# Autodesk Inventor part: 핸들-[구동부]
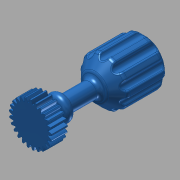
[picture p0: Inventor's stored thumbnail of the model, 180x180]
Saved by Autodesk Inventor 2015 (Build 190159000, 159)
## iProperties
Created: 2017-04
Part Number: 핸들-[구동부]
Material: 강철, 연강
Document SubType Name: Modeling
Designer: mduedu
Categories: <?xml version="1.0" encoding="UTF-16"?> <MemberInstance><Categories><FamilyTemplate><FamilyTemplateParameter ValueType="xs:double" Id="1" ObjectReferenceKey="da
Density: 7.86 g/cm^3
Mass: 209.322 g
Surface Area: 78.6047 cm^2
Volume: 26.6313 cm^3
Appearance: 청록색
CustomPartVersion: 1
Author: mduedu
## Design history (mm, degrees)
sketch "Sketch1"
  geometry: C1 r 13.5 at (0, 0)
  constraints: 1 centre point
  dimensions: "d0" = 27 diameter of C1 (= da_da)
extrude "Extrusion1" new body sketch "Sketch1" distance "d1" = 10 (= da_b); taper "d2" = 0 deg
workplane "Work Plane2"
sketch "Sketch2"
  geometry: C1 r 13.5 at (0, 0) reference; C2 r 12.5 at (0, 0)
  constraints: 1 centre point, 1 coincident
  dimensions: "d3" = 25 diameter of C2 (= da_dw)
feature "피치 지름" sketch "Sketch2" dims "d4" = 10, "d5" = 0
workplane "Work Plane8"
workplane "Work Plane9"
feature "스퍼 기어" dims "da_b" = 10, "da_d" = 25, "da_aw" = 25, "da_da" = 27, "da_df" = 22.5, "da_dw" = 25, angle "da_beta" = 0 deg, "da_lefttooth" = 0, "da_righttooth" = 0
sketch "스케치3"
  geometry: C1 r 5 at (0, 0); 1 further point
  constraints: 1 centre point, 1 coincident
  dimensions: "d49" = 10 diameter of C1
extrude "돌출2" join sketch "스케치3" distance "d50" = 60; taper "d51" = 0 deg
sketch "스케치4"
  geometry: C1 r 15 at (0, 0); 1 further point
  constraints: 1 centre point, 1 coincident
  dimensions: "d52" = 30 diameter of C1
extrude "돌출3" join sketch "스케치4" distance "d53" = 30; taper "d54" = 0 deg
chamfer "모따기1" distance "d55" = 7; stored, may be unused: second distance "d56" = 2, angle "d57" = 45 deg
sketch "스케치5"
  geometry: L1 (0, 2.2)-(0, -13.2) reference; L2 (0, -5)-(8, -5); L3 (8, -5)-(8, -11); L4 (8, -11)-(0, -11); L5 (0, -11)-(0, -5); 1 further point
  constraints: 8 end point, 2 parallel, 1 horizontal, 1 perpendicular, 1 point on line
  dimensions: "d58" = 5 distance from line of L2 point (0, 0); "d59" = 6 distance of L2.end L3.end; "d60" = 16 diameter of L3 L1
revolve "회전1" sketch "스케치5" stored, may be unused: angle "d61" = 90 deg
fillet "모깎기1" dims "d62" = 3
fillet "모깎기2" dims "d65" = 3
sketch "스케치9"
  geometry: L1 (15, -60)-(-15, -60) reference; L2 (0, -60)-(0, 0); L3 (0, -66.771)-(0, -60); A1 r 20 centre (0, -46.771) between (0, -66.771) and (15, -60)
  constraints: 4 end point, 2 point on circle, 1 centre point, 1 collinear, 1 line through centre, 1 midpoint, 1 perpendicular
  dimensions: "d84" = 20 radius of A1
revolve "회전4" sketch "스케치9" stored, may be unused: angle "d86" = 90 deg
fillet "모깎기3" dims "d72" = 3
sketch "스케치6"
  geometry: C1 r 2.5 at (0, 15); 2 further points
  constraints: 2 vertical alignment, 1 centre point, 1 other
  dimensions: "d66" = 5 diameter of C1
extrude "돌출4" cut sketch "스케치6" stored distance "d67" = 60; taper "d68" = 0 deg
fillet "모깎기4" dims "d73" = 1
node "작업 평면12"
sketch "스케치10"
  geometry: C1 r 6 at (0, 0); 1 further point
  constraints: 1 centre point, 1 coincident
  dimensions: "d87" = 12 diameter of C1
extrude "돌출5" cut sketch "스케치10" distance "d88" = 5; taper "d89" = 0 deg
fillet "모깎기5" dims "d90" = 1
body "Solid1"
pattern_circular "원형 패턴2" dims angle "d75" = 360 deg
body "Srf1"
other parameters: "d16" = 25 (= da_aw), "d17" = 0, "d34" = 1.25664 (computed from da_z), "d39" = 0, "d41" = 0, "d43" = 25 (= da_aw), "d46" = 25 (= da_aw), "d47" = 0, "d48" = 0
